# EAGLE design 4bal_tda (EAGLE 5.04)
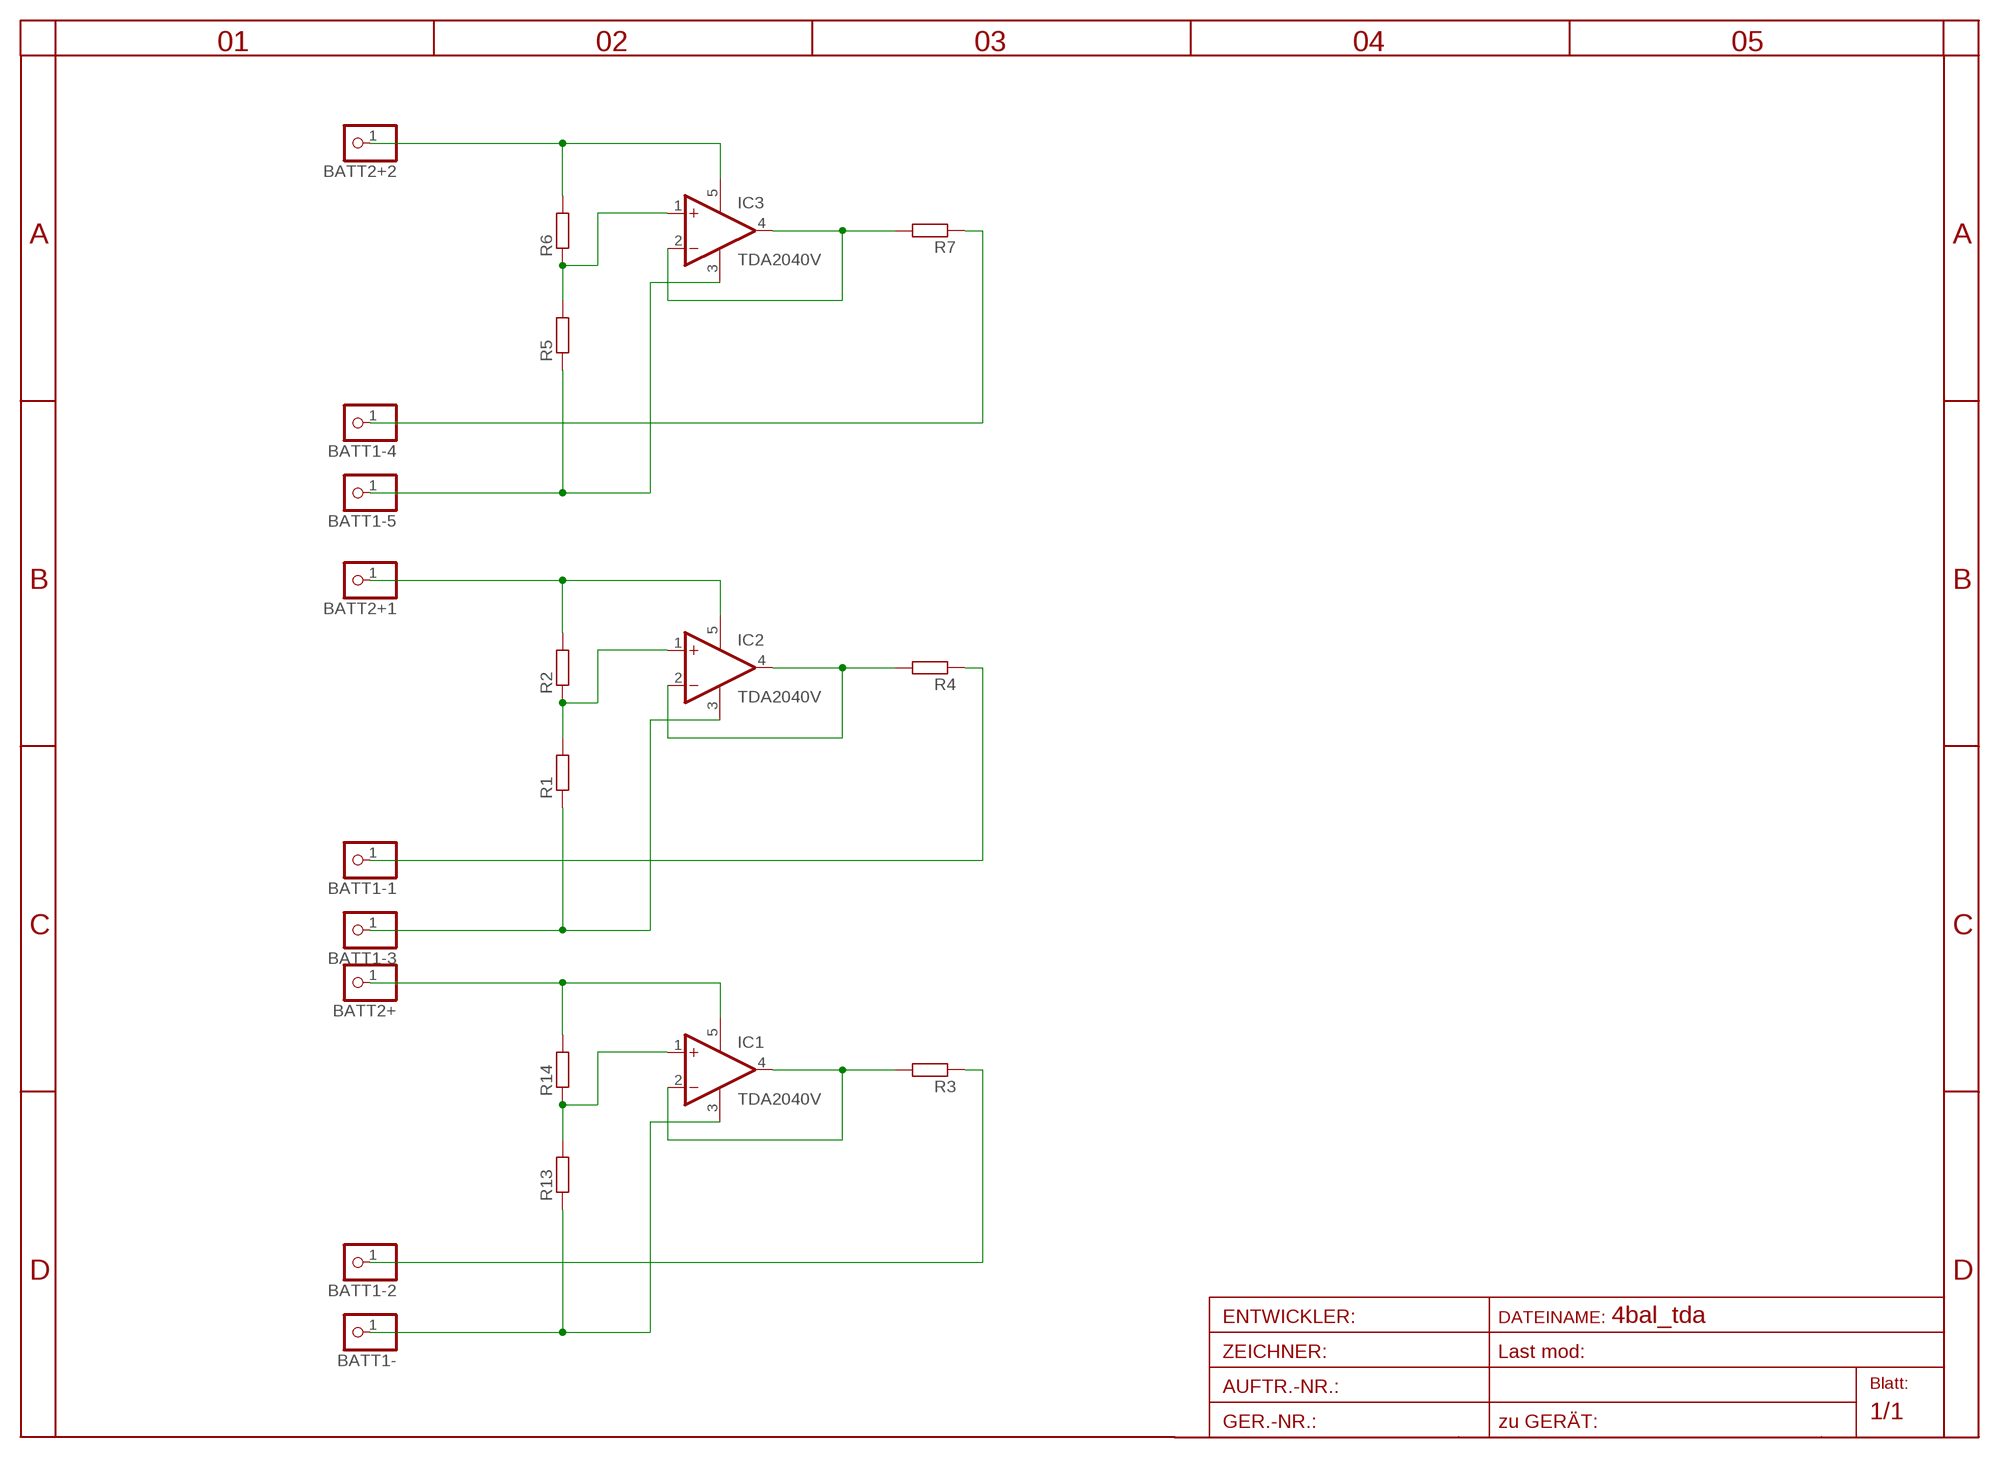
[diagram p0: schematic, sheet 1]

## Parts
BATT1-  PINHD-1X1  [1X01]
BATT1-1  PINHD-1X1  [1X01]
BATT1-2  PINHD-1X1  [1X01]
BATT1-3  PINHD-1X1  [1X01]
BATT1-4  PINHD-1X1  [1X01]
BATT1-5  PINHD-1X1  [1X01]
BATT2+  PINHD-1X1  [1X01]
BATT2+1  PINHD-1X1  [1X01]
BATT2+2  PINHD-1X1  [1X01]
IC1  TDA2040V  [CB360]
IC2  TDA2040V  [CB360]
IC3  TDA2040V  [CB360]
R1  R-EU_0204/5  [0204/5]
R2  R-EU_0204/5  [0204/5]
R3  R-EU_0309/10  [0309/10]
R4  R-EU_0309/10  [0309/10]
R5  R-EU_0204/5  [0204/5]
R6  R-EU_0204/5  [0204/5]
R7  R-EU_0309/10  [0309/10]
R13  R-EU_0204/5  [0204/5]
R14  R-EU_0204/5  [0204/5]

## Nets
B1: BATT1-2.1 R3.1
B2: BATT1-1.1 R4.1
B3: BATT1-4.1 R7.1
N$1: BATT1-.1 IC1.3(V-) R13.1
N$2: IC1.2(-IN) IC1.4(OUT) R3.2
N$3: BATT2+.1 IC1.5(V+) R14.2
N$4: IC2.1(+IN) R1.2 R2.1
N$5: IC2.2(-IN) IC2.4(OUT) R4.2
N$6: BATT1-3.1 IC2.3(V-) R1.1
N$7: BATT2+1.1 IC2.5(V+) R2.2
N$8: IC3.1(+IN) R5.2 R6.1
N$9: IC3.2(-IN) IC3.4(OUT) R7.2
N$10: BATT1-5.1 IC3.3(V-) R5.1
N$11: BATT2+2.1 IC3.5(V+) R6.2
N$28: IC1.1(+IN) R13.2 R14.1

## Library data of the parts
BATT1- BATT1-1-BATT1-5 BATT2+ BATT2+1 BATT2+2 = pinhead:PINHD-1X1: PIN HEADER
IC1-IC3 = linear:TDA2040: Power OP AMP
R1-R7 R13 R14 = rcl-2:R-EU_: RESISTOR, European symbol

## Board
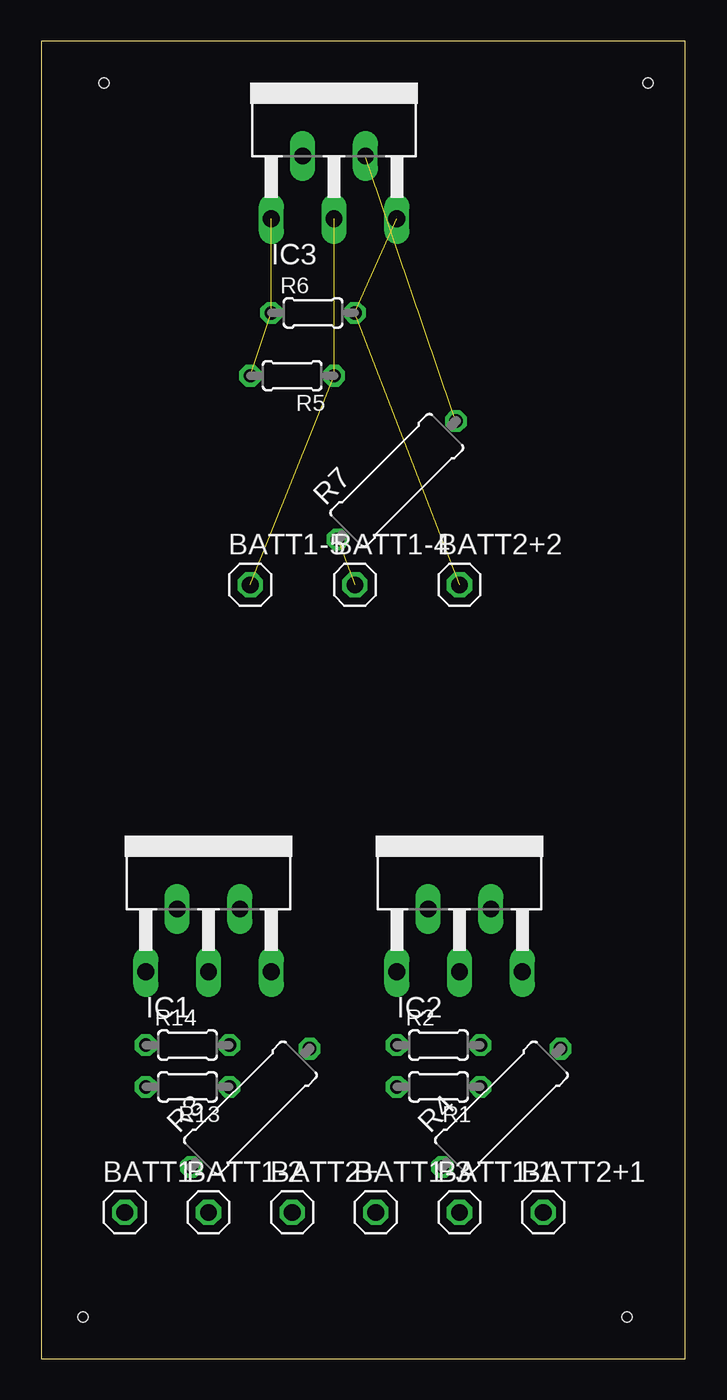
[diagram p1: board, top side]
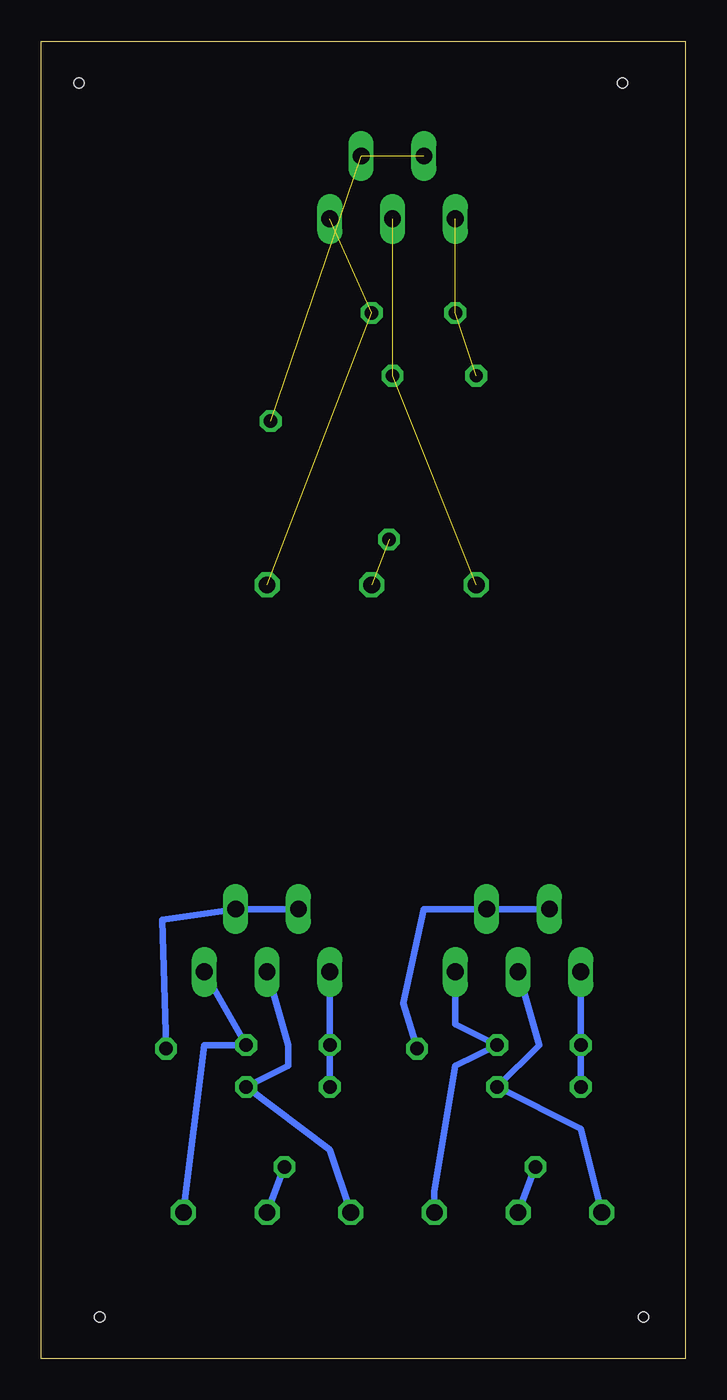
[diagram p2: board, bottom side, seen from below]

Size 39.12 x 80 mm. Coordinates in mm from the lower left corner, seen from the top.
Outline: 0,0 39.12,0 39.12,80 0,80 0,0
Copper layers (1*16): Top 0.035mm / dielectric 1.5mm / Bottom 0.035mm
Design rules "default": minimum track width 10mil, minimum drill 24mil, track to track 8mil, track to pad 8mil, pad to pad 8mil, via to via 8mil, smd to smd 8mil, copper to edge 40mil, drill to drill 8mil, minimum pad ring 10mil, minimum via ring 8mil, stop-mask expansion 4mil, vias tented up to drill 0mil, thermal gap 10mil
Holes 0.6 mm at 2.54,2.54 35.56,2.54 36.83,77.47 3.81,77.47

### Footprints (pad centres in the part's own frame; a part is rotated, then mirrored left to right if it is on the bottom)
1X01 = drill 1.016 octagon: 1 0,0
CB360 = drill 1.016 long: 1 -3.81,-8.255; 2 -1.905,-4.445; 3 0,-8.255; 4 1.905,-4.445; 5 3.81,-8.255
0204/5 = drill 0.813 octagon: 1 -2.54,0; 2 2.54,0
0309/10 = drill 0.813 octagon: 1 -5.08,0; 2 5.08,0

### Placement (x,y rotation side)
BATT1-  5.08,8.89 0 top
BATT1-1  25.4,8.89 0 top
BATT1-2  10.16,8.89 0 top
BATT1-3  20.32,8.89 0 top
BATT1-4  19.05,46.99 0 top
BATT1-5  12.7,46.99 0 top
BATT2+  15.24,8.89 0 top
BATT2+1  30.48,8.89 0 top
BATT2+2  25.4,46.99 0 top
IC1  10.16,31.75 0 top
IC2  25.4,31.75 0 top
IC3  17.78,77.47 0 top
R1  24.13,16.51 180 top
R2  24.13,19.05 0 top
R3  12.7,15.24 45 top
R4  27.94,15.24 45 top
R5  15.24,59.69 180 top
R6  16.51,63.5 0 top
R7  21.59,53.34 45 top
R13  8.89,16.51 180 top
R14  8.89,19.05 0 top

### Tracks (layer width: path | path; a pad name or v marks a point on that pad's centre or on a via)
B1
  Bottom 0.406: R3.1 BATT1-2.1
B2
  Bottom 0.406: R4.1 BATT1-1.1
B3  (1 unrouted)
N$1
  Bottom 0.406: IC1.3 8.89,19.05 R13.1 6.35,13.97 BATT1-.1
N$2
  Bottom 0.406: R3.2 17.14,21.59 15.88,27.3 IC1.4 IC1.2
N$3
  Bottom 0.406: BATT2+.1 15.24,10.16 13.97,17.78 R14.2 13.97,20.32 IC1.5
N$4
  Bottom 0.406: R1.2 R2.1 IC2.1
N$5
  Bottom 0.406: R4.2 31.75,26.67 IC2.4 IC2.2
N$6
  Bottom 0.406: IC2.3 24.13,19.05 24.13,17.78 R1.1 21.59,12.7 BATT1-3.1
N$7
  Bottom 0.406: BATT2+1.1 29.21,19.05 R2.2 IC2.5
N$8  (2 unrouted)
N$9  (2 unrouted)
N$10  (2 unrouted)
N$11  (2 unrouted)
N$28
  Bottom 0.406: IC1.1 R14.1 R13.2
